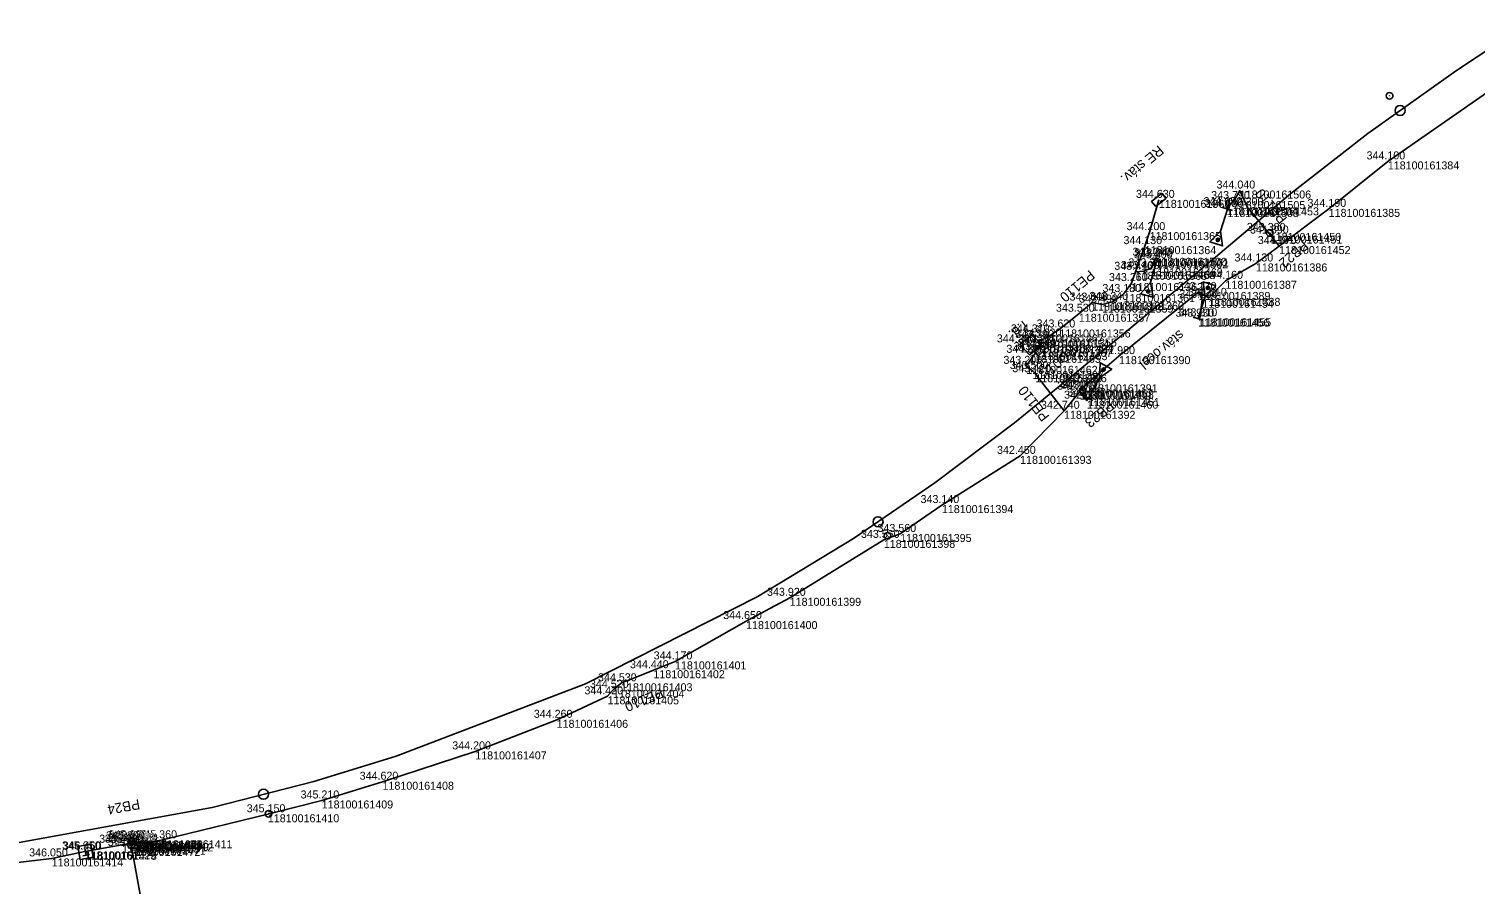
# Model space of a CAD drawing. Extents: x -732194 to -724760, y -944826 to -941477.
# Drawn here: x -726803.1 to -726586.2, y -941994.8 to -941866.5 of the extents above; entities that cross this region are included whole.
import ezdxf

# ---------------------------------------------------------------- set-up
doc = ezdxf.new("R2010")
doc.units = 0
for name, color, linetype in [('Vrstva 1', 7, 'Continuous'), ('Vrstva 25', 7, 'Continuous'), ('Vrstva 26', 7, 'Continuous'), ('Vrstva 28', 7, 'Continuous'), ('Vrstva 31', 7, 'Continuous'), ('Vrstva 33', 7, 'Continuous'), ('Vrstva 35', 7, 'Continuous'), ('Vrstva 36', 7, 'Continuous'), ('Vrstva 4', 7, 'Continuous'), ('Vrstva 6', 7, 'Continuous'), ('Vrstva 60', 7, 'Continuous'), ('Vrstva 61', 7, 'Continuous'), ('Vrstva 7', 7, 'Continuous')]:
    doc.layers.add(name, color=color, linetype=linetype)

msp = doc.modelspace()

# ---------------------------------------------------------------- linework, layer by layer
at = {"layer": 'Vrstva 1'}
msp.add_lwpolyline([(-726579.57, -941866.53), (-726589.02, -941872.75), (-726602.3, -941882.23), (-726613.83, -941891.22), (-726625.12, -941900.77), (-726638.15, -941911.63), (-726655.27, -941925.61), (-726667.22, -941934.63), (-726679.44, -941942.96), (-726693.78, -941951.66), (-726719.62, -941964.76), (-726748.05, -941975.61), (-726760.36, -941979.39), (-726775.65, -941983.31), (-726804.56, -941988.54), (-726832.05, -941990.67), (-726859.67, -941990.82), (-726884.47, -941990.59), (-726908.99, -941990.36), (-726961.75, -941989.93), (-727002.29, -941989.53)], dxfattribs=at)
at = {"layer": 'Vrstva 25'}
for points in [[(-726633.19, -941891.15), (-726632.55, -941891.91), (-726634.09, -941893.19), (-726634.73, -941892.43), (-726633.19, -941891.15)], [(-726650.91, -941913.48), (-726650.25, -941914.23), (-726651.75, -941915.56), (-726652.41, -941914.81), (-726650.91, -941913.48)]]:
    msp.add_lwpolyline(points, dxfattribs=at)
at = {"layer": 'Vrstva 26'}
for points in [[(-726580.39, -941873.25), (-726599.3, -941886.4), (-726608.17, -941893.52), (-726615.6, -941899.1), (-726619.09, -941901.71), (-726623.65, -941904.31), (-726626.12, -941906.87), (-726627.62, -941905.98), (-726639.62, -941915.61), (-726644.54, -941919.84), (-726645.19, -941920.6), (-726645.48, -941920.93), (-726647.86, -941923.81)], [(-726637.12, -941902.96), (-726635.75, -941899.11), (-726635.03, -941897.01), (-726633.64, -941892.17)], [(-726651.33, -941914.52), (-726651.77, -941913.2), (-726650.65, -941912.97), (-726648.58, -941911.61), (-726645.64, -941909.25), (-726643.65, -941907.58), (-726642.16, -941907.88), (-726640.59, -941907.48), (-726638.93, -941906.3), (-726637.72, -941904.65), (-726637.12, -941902.96)], [(-726652.59, -941917.84), (-726653.53, -941917.07), (-726652.06, -941915.01)], [(-726647.86, -941923.81), (-726652.16, -941918.32), (-726652.59, -941917.84)], [(-726647.86, -941923.81), (-726654.45, -941930.57), (-726666.18, -941937.95), (-726672.44, -941942.28), (-726674.89, -941943.17), (-726689.01, -941951.86), (-726695.55, -941955.35), (-726706.21, -941961.4), (-726709.45, -941962.72), (-726714.3, -941964.68), (-726715.51, -941965.66), (-726716.32, -941966.64), (-726723.96, -941970.16), (-726736.17, -941974.9), (-726750.08, -941979.45), (-726759.2, -941982.26), (-726767.28, -941984.33), (-726783.3, -941988.23), (-726786.19, -941988.71), (-726786.85, -941988.6)], [(-726788.31, -941988.87), (-726789.14, -941988.9), (-726794.75, -941989.89)], [(-726786.85, -941988.6), (-726787.32, -941989.21), (-726788.12, -941989.39), (-726788.31, -941988.87)], [(-726794.75, -941989.89), (-726799.69, -941990.95), (-726813.85, -941992.61)]]:
    msp.add_lwpolyline(points, dxfattribs=at)
at = {"layer": 'Vrstva 28'}
for p, q in [((-726617.05, -941897.16), (-726616.97, -941897.1)), ((-726617.01, -941897.13), (-726616.83, -941897.52)), ((-726645.13, -941920.8), (-726645.05, -941920.74)), ((-726787.74, -941988.36), (-726787.64, -941988.34))]:
    msp.add_line(p, q, dxfattribs=at)
for points in [[(-726580.39, -941873.25), (-726599.3, -941886.4), (-726608.17, -941893.52), (-726615.6, -941899.1), (-726619.09, -941901.71), (-726623.65, -941904.31), (-726626.12, -941906.87), (-726627.62, -941905.98), (-726639.62, -941915.61), (-726644.54, -941919.84), (-726645.19, -941920.6), (-726645.48, -941920.93), (-726647.86, -941923.81)], [(-726623.35, -941893.55), (-726623.49, -941893.26), (-726622.39, -941892.35), (-726621.51, -941890.77), (-726620.34, -941893.3)], [(-726616.83, -941897.52), (-726620.34, -941893.3)], [(-726616.83, -941897.52), (-726615.6, -941899.1)], [(-726651.77, -941913.2), (-726650.65, -941912.97), (-726648.58, -941911.61), (-726645.64, -941909.25), (-726643.65, -941907.58), (-726642.16, -941907.88), (-726640.59, -941907.48), (-726638.93, -941906.3), (-726637.72, -941904.65), (-726637.12, -941902.96), (-726635.89, -941902.85), (-726634.77, -941902.44), (-726634.14, -941900.86)], [(-726634.14, -941900.86), (-726633.84, -941900.97), (-726633.96, -941901.24)], [(-726627.62, -941905.98), (-726627.12, -941907.16), (-726627.51, -941909.93), (-726627.76, -941909.99)], [(-726652.59, -941917.84), (-726653.53, -941917.07), (-726652.06, -941915.01)], [(-726647.86, -941923.81), (-726652.16, -941918.32), (-726652.59, -941917.84)], [(-726645.48, -941920.93), (-726644.43, -941922.29), (-726644.21, -941921.9)], [(-726645.19, -941920.6), (-726645.09, -941920.77)], [(-726647.86, -941923.81), (-726654.45, -941930.57), (-726666.18, -941937.95), (-726672.44, -941942.28), (-726674.89, -941943.17), (-726689.01, -941951.86), (-726695.55, -941955.35), (-726706.21, -941961.4), (-726709.45, -941962.72), (-726714.3, -941964.68), (-726715.51, -941965.66), (-726716.32, -941966.64), (-726723.96, -941970.16), (-726736.17, -941974.9), (-726750.08, -941979.45), (-726759.2, -941982.26), (-726767.28, -941984.33), (-726783.3, -941988.23), (-726786.19, -941988.71), (-726786.85, -941988.6)], [(-726788.31, -941988.87), (-726789.14, -941988.9), (-726794.75, -941989.89)], [(-726788.31, -941988.87), (-726788.13, -941988.39), (-726787.81, -941988.23), (-726787.69, -941988.35)], [(-726786.85, -941988.6), (-726787.32, -941989.21), (-726788.12, -941989.39), (-726788.31, -941988.87)], [(-726788.31, -941988.87), (-726787.83, -941988.66)], [(-726794.63, -941989.96), (-726794.75, -941989.89), (-726799.69, -941990.95), (-726813.85, -941992.61)]]:
    msp.add_lwpolyline(points, dxfattribs=at)
for centre in [(-726617.01, -941897.13), (-726645.09, -941920.77), (-726787.69, -941988.35)]:
    msp.add_circle(centre, 0.5, dxfattribs=at)
at = {"layer": 'Vrstva 31'}
for points in [[(-726580.39, -941873.25), (-726599.3, -941886.4), (-726608.17, -941893.52), (-726615.6, -941899.1), (-726619.09, -941901.71), (-726623.65, -941904.31), (-726626.12, -941906.87), (-726627.62, -941905.98), (-726639.62, -941915.61), (-726644.54, -941919.84), (-726645.19, -941920.6), (-726645.48, -941920.93), (-726647.86, -941923.81)], [(-726647.86, -941923.81), (-726654.45, -941930.57), (-726666.18, -941937.95), (-726672.44, -941942.28), (-726674.89, -941943.17), (-726689.01, -941951.86), (-726695.55, -941955.35), (-726706.21, -941961.4), (-726709.45, -941962.72), (-726714.3, -941964.68), (-726715.51, -941965.66), (-726716.32, -941966.64), (-726723.96, -941970.16), (-726736.17, -941974.9), (-726750.08, -941979.45), (-726759.2, -941982.26), (-726767.28, -941984.33), (-726783.3, -941988.23), (-726786.19, -941988.71), (-726786.85, -941988.6)], [(-726788.31, -941988.87), (-726789.14, -941988.9), (-726794.75, -941989.89)], [(-726786.85, -941988.6), (-726787.32, -941989.21), (-726788.12, -941989.39), (-726788.31, -941988.87)], [(-726794.63, -941989.96), (-726794.75, -941989.89), (-726799.69, -941990.95), (-726813.85, -941992.61)]]:
    msp.add_lwpolyline(points, dxfattribs=at)
at = {"layer": 'Vrstva 33'}
for p, q in [((-726794.54, -941990.45), (-726794.72, -941989.47)), ((-726794.05, -941990.36), (-726795.03, -941990.54))]:
    msp.add_line(p, q, dxfattribs=at)
msp.add_lwpolyline([(-726793.47, -941990.77), (-726795.44, -941991.12), (-726795.79, -941989.15), (-726793.82, -941988.8), (-726793.47, -941990.77)], dxfattribs=at)
at = {"layer": 'Vrstva 35'}
for points in [[(-726616.83, -941897.52), (-726620.34, -941893.3)], [(-726651.77, -941913.2), (-726650.65, -941912.97), (-726648.58, -941911.61), (-726645.64, -941909.25), (-726643.65, -941907.58), (-726642.16, -941907.88), (-726640.59, -941907.48), (-726638.93, -941906.3), (-726637.72, -941904.65), (-726637.12, -941902.96), (-726635.89, -941902.85), (-726634.77, -941902.44), (-726634.14, -941900.86)], [(-726623.65, -941904.31), (-726626.12, -941906.87), (-726627.62, -941905.98), (-726639.62, -941915.61)], [(-726647.86, -941923.81), (-726652.16, -941918.32)], [(-726709.45, -941962.72), (-726714.3, -941964.68), (-726715.51, -941965.66)]]:
    msp.add_lwpolyline(points, dxfattribs=at)
at = {"layer": 'Vrstva 36'}
msp.add_lwpolyline([(-726651.19, -941913.97), (-726653.06, -941915.41), (-726654.51, -941913.85), (-726652.63, -941912.35), (-726651.19, -941913.97)], dxfattribs=at)
at = {"layer": 'Vrstva 4'}
for p, q in [((-726622.61, -941893.79), (-726624.09, -941893.31)), ((-726624.58, -941898.06), (-726625.01, -941898.28)), ((-726633.21, -941901.45), (-726634.71, -941901.03)), ((-726626.51, -941905.49), (-726626.07, -941905.27)), ((-726635.02, -941905.79), (-726635.45, -941906.03)), ((-726628.5, -941909.75), (-726627.02, -941910.23)), ((-726642.16, -941917.7), (-726641.69, -941917.56)), ((-726644.89, -941921.53), (-726643.53, -941922.27))]:
    msp.add_line(p, q, dxfattribs=at)
for points in [[(-726623.35, -941893.55), (-726624.41, -941896.86), (-726624.08, -941899.07), (-726625.98, -941898.47), (-726624.41, -941896.86)], [(-726633.96, -941901.24), (-726634.89, -941904.59), (-726634.48, -941906.79), (-726636.41, -941906.26), (-726634.89, -941904.59)], [(-726627.76, -941909.99), (-726626.68, -941906.68), (-726627, -941904.47), (-726625.1, -941905.08), (-726626.68, -941906.68)], [(-726644.21, -941921.9), (-726642.55, -941918.85), (-726642.46, -941916.61), (-726640.7, -941917.56), (-726642.55, -941918.85)]]:
    msp.add_lwpolyline(points, dxfattribs=at)
for centre in [(-726624.79, -941898.17), (-726626.29, -941905.38), (-726635.23, -941905.91), (-726641.92, -941917.63)]:
    msp.add_circle(centre, 0.248, dxfattribs=at)
at = {"layer": 'Vrstva 6'}
for p, q in [((-726787.92, -941988.17), (-726787.74, -941989.15)), ((-726785.88, -941988.31), (-726787.83, -941988.66)), ((-726778.93, -942037.86), (-726787.83, -941988.66))]:
    msp.add_line(p, q, dxfattribs=at)
at = {"layer": 'Vrstva 60'}
for p, q in [((-726599.3, -941886.4), (-726599.3, -941886.4)), ((-726633.64, -941892.17), (-726633.64, -941892.17)), ((-726621.51, -941890.77), (-726621.51, -941890.77)), ((-726623.49, -941893.26), (-726623.49, -941893.26)), ((-726623.35, -941893.55), (-726623.35, -941893.55)), ((-726622.39, -941892.35), (-726622.39, -941892.35)), ((-726620.34, -941893.3), (-726620.34, -941893.3)), ((-726608.17, -941893.52), (-726608.17, -941893.52)), ((-726635.03, -941897.01), (-726635.03, -941897.01)), ((-726617.01, -941897.13), (-726617.01, -941897.13)), ((-726616.83, -941897.52), (-726616.83, -941897.52)), ((-726635.75, -941899.11), (-726635.75, -941899.11)), ((-726634.14, -941900.86), (-726634.14, -941900.86)), ((-726615.6, -941899.1), (-726615.6, -941899.1)), ((-726637.12, -941902.96), (-726637.12, -941902.96)), ((-726635.89, -941902.85), (-726635.89, -941902.85)), ((-726634.77, -941902.44), (-726634.77, -941902.44)), ((-726633.96, -941901.24), (-726633.96, -941901.24)), ((-726633.84, -941900.97), (-726633.84, -941900.97)), ((-726619.09, -941901.71), (-726619.09, -941901.71)), ((-726637.72, -941904.65), (-726637.72, -941904.65)), ((-726623.65, -941904.31), (-726623.65, -941904.31)), ((-726638.93, -941906.3), (-726638.93, -941906.3)), ((-726627.62, -941905.98), (-726627.62, -941905.98)), ((-726627.12, -941907.16), (-726627.12, -941907.16)), ((-726626.12, -941906.87), (-726626.12, -941906.87)), ((-726645.64, -941909.25), (-726645.64, -941909.25)), ((-726643.65, -941907.58), (-726643.65, -941907.58)), ((-726642.16, -941907.88), (-726642.16, -941907.88)), ((-726640.59, -941907.48), (-726640.59, -941907.48)), ((-726648.58, -941911.61), (-726648.58, -941911.61)), ((-726627.76, -941909.99), (-726627.76, -941909.99)), ((-726627.51, -941909.93), (-726627.51, -941909.93)), ((-726654.51, -941913.85), (-726654.51, -941913.85)), ((-726652.63, -941912.35), (-726652.63, -941912.35)), ((-726651.77, -941913.2), (-726651.77, -941913.2)), ((-726650.65, -941912.97), (-726650.65, -941912.97)), ((-726653.06, -941915.41), (-726653.06, -941915.41)), ((-726652.06, -941915.01), (-726652.06, -941915.01)), ((-726651.33, -941914.52), (-726651.33, -941914.52)), ((-726651.19, -941913.97), (-726651.19, -941913.97)), ((-726639.62, -941915.61), (-726639.62, -941915.61)), ((-726653.53, -941917.07), (-726653.53, -941917.07)), ((-726652.59, -941917.84), (-726652.59, -941917.84)), ((-726652.16, -941918.32), (-726652.16, -941918.32)), ((-726644.54, -941919.84), (-726644.54, -941919.84)), ((-726645.48, -941920.93), (-726645.48, -941920.93)), ((-726645.19, -941920.6), (-726645.19, -941920.6)), ((-726645.09, -941920.77), (-726645.09, -941920.77)), ((-726644.43, -941922.29), (-726644.43, -941922.29)), ((-726644.21, -941921.9), (-726644.21, -941921.9)), ((-726647.86, -941923.81), (-726647.86, -941923.81)), ((-726654.45, -941930.57), (-726654.45, -941930.57)), ((-726666.18, -941937.95), (-726666.18, -941937.95)), ((-726674.89, -941943.17), (-726674.89, -941943.17)), ((-726672.44, -941942.28), (-726672.44, -941942.28)), ((-726689.01, -941951.86), (-726689.01, -941951.86)), ((-726695.55, -941955.35), (-726695.55, -941955.35)), ((-726706.21, -941961.4), (-726706.21, -941961.4)), ((-726709.45, -941962.72), (-726709.45, -941962.72)), ((-726715.51, -941965.66), (-726715.51, -941965.66)), ((-726714.3, -941964.68), (-726714.3, -941964.68)), ((-726716.32, -941966.64), (-726716.32, -941966.64)), ((-726723.96, -941970.16), (-726723.96, -941970.16)), ((-726736.17, -941974.9), (-726736.17, -941974.9)), ((-726750.08, -941979.45), (-726750.08, -941979.45)), ((-726759.2, -941982.26), (-726759.2, -941982.26)), ((-726767.28, -941984.33), (-726767.28, -941984.33)), ((-726789.14, -941988.9), (-726789.14, -941988.9)), ((-726788.31, -941988.87), (-726788.31, -941988.87)), ((-726788.13, -941988.39), (-726788.13, -941988.39)), ((-726788.12, -941989.39), (-726788.12, -941989.39)), ((-726787.83, -941988.66), (-726787.83, -941988.66)), ((-726787.81, -941988.23), (-726787.81, -941988.23)), ((-726787.69, -941988.35), (-726787.69, -941988.35)), ((-726787.32, -941989.21), (-726787.32, -941989.21)), ((-726786.85, -941988.6), (-726786.85, -941988.6)), ((-726786.19, -941988.71), (-726786.19, -941988.71)), ((-726783.3, -941988.23), (-726783.3, -941988.23)), ((-726799.69, -941990.95), (-726799.69, -941990.95)), ((-726794.75, -941989.89), (-726794.75, -941989.89)), ((-726794.63, -941989.96), (-726794.63, -941989.96))]:
    msp.add_line(p, q, dxfattribs=at)
at = {"layer": 'Vrstva 7'}
for p, q in [((-726599.07, -941876.6), (-726598.99, -941876.54)), ((-726674.37, -941942.59), (-726674.28, -941942.53)), ((-726767.23, -941984.28), (-726767.13, -941984.25))]:
    msp.add_line(p, q, dxfattribs=at)
for centre, radius in [((-726599.03, -941876.57), 0.5), ((-726597.46, -941878.77), 0.75), ((-726675.76, -941940.45), 0.75), ((-726674.32, -941942.56), 0.5), ((-726767.93, -941981.33), 0.75), ((-726767.18, -941984.26), 0.5)]:
    msp.add_circle(centre, radius, dxfattribs=at)

# ---------------------------------------------------------------- texts
at = {"layer": 'Vrstva 25'}
for s, rotation, p in [('RE stáv.', 219.8056, (-726633.7, -941883.9)), ('RO01', 221.6335, (-726646.73, -941913.76))]:
    msp.add_text(s, height=1.5, rotation=rotation, dxfattribs=at).set_placement(p)
at = {"layer": 'Vrstva 28'}
for s, rotation, p in [('PB22', 220.2486, (-726612.02, -941898.18)), ('PB23', 219.2246, (-726641.1, -941922.2)), ('PB24', 190.2527, (-726786.62, -941982.06))]:
    msp.add_text(s, height=1.5, rotation=rotation, dxfattribs=at).set_placement(p)
at = {"layer": 'Vrstva 36'}
for s, rotation, p in [('PE110', 129.7521, (-726614.31, -941894.97)), ('PE110', 220.0032, (-726644.04, -941902.62)), ('r.d.', 217.5982, (-726654.04, -941910.21)), ('stáv.ocel', 218.747, (-726630.55, -941911.59)), ('PE110', 128.0695, (-726649.96, -941924.65)), ('PE110', 202.0048, (-726708.33, -941965.35))]:
    msp.add_text(s, height=1.5, rotation=rotation, dxfattribs=at).set_placement(p)
at = {"layer": 'Vrstva 6'}
msp.add_text('  A A A A ', height=1, rotation=10.2527, dxfattribs=at).set_placement((-726787.65, -941989.64))
at = {"layer": 'Vrstva 60'}
for s, p in [('118100161384', (-726599.3, -941887.6)), ('118100161366', (-726633.64, -941893.37)), ('118100161506', (-726621.51, -941891.97)), ('118100161504', (-726623.49, -941894.46)), ('118100161503', (-726623.35, -941894.75)), ('118100161505', (-726622.39, -941893.55)), ('118100161453', (-726620.34, -941894.5)), ('118100161385', (-726608.17, -941894.72)), ('118100161365', (-726635.03, -941898.21)), ('118100161450', (-726617.01, -941898.33)), ('118100161451', (-726616.83, -941898.72)), ('118100161364', (-726635.75, -941900.31)), ('118100161500', (-726634.14, -941902.06)), ('118100161501', (-726633.84, -941902.17)), ('118100161452', (-726615.6, -941900.3)), ('118100161363', (-726637.12, -941904.16)), ('118100161468', (-726635.89, -941904.05)), ('118100161469', (-726634.77, -941903.64)), ('118100161502', (-726633.96, -941902.44)), ('118100161386', (-726619.09, -941902.91)), ('118100161362', (-726637.72, -941905.85)), ('118100161387', (-726623.65, -941905.51)), ('118100161360', (-726640.59, -941908.68)), ('118100161361', (-726638.93, -941907.5)), ('118100161389', (-726627.62, -941907.18)), ('118100161454', (-726627.12, -941908.36)), ('118100161388', (-726626.12, -941908.07)), ('118100161357', (-726645.64, -941910.45)), ('118100161358', (-726643.65, -941908.78)), ('118100161359', (-726642.16, -941909.08)), ('118100161356', (-726648.58, -941912.81)), ('118100161456', (-726627.76, -941911.19)), ('118100161455', (-726627.51, -941911.13)), ('118100161466', (-726654.51, -941915.05)), ('118100161467', (-726652.63, -941913.55)), ('118100161354', (-726651.77, -941914.4)), ('118100161464', (-726651.19, -941915.17)), ('118100161355', (-726650.65, -941914.17)), ('118100161465', (-726653.06, -941916.61)), ('118100161463', (-726652.06, -941916.21)), ('118100161367', (-726651.33, -941915.72)), ('118100161390', (-726639.62, -941916.81)), ('118100161462', (-726653.53, -941918.27)), ('118100161397', (-726652.59, -941919.04)), ('118100161396', (-726652.16, -941919.52)), ('118100161391', (-726644.54, -941921.04)), ('118100161459', (-726645.48, -941922.13)), ('118100161457', (-726645.19, -941921.8)), ('118100161458', (-726645.09, -941921.97)), ('118100161460', (-726644.43, -941923.49)), ('118100161461', (-726644.21, -941923.1)), ('118100161392', (-726647.86, -941925.01)), ('118100161393', (-726654.45, -941931.77)), ('118100161394', (-726666.18, -941939.15)), ('118100161398', (-726674.89, -941944.37)), ('118100161395', (-726672.44, -941943.48)), ('118100161399', (-726689.01, -941953.06)), ('118100161400', (-726695.55, -941956.55)), ('118100161401', (-726706.21, -941962.6)), ('118100161402', (-726709.45, -941963.92)), ('118100161404', (-726715.51, -941966.86)), ('118100161403', (-726714.3, -941965.88)), ('118100161405', (-726716.32, -941967.84)), ('118100161406', (-726723.96, -941971.36)), ('118100161407', (-726736.17, -941976.1)), ('118100161408', (-726750.08, -941980.65)), ('118100161409', (-726759.2, -941983.46)), ('118100161410', (-726767.28, -941985.53)), ('118100161529', (-726794.75, -941991.09)), ('118100161413', (-726789.14, -941990.1)), ('118100161473', (-726788.31, -941990.07)), ('118100161474', (-726788.13, -941989.59)), ('118100161472', (-726788.12, -941990.59)), ('118100161477', (-726787.83, -941989.86)), ('118100161475', (-726787.81, -941989.43)), ('118100161476', (-726787.69, -941989.55)), ('118100161471', (-726787.32, -941990.41)), ('118100161470', (-726786.85, -941989.8)), ('118100161412', (-726786.19, -941989.91)), ('118100161411', (-726783.3, -941989.43)), ('118100161414', (-726799.69, -941992.15)), ('118100161478', (-726794.63, -941991.16))]:
    msp.add_text(s, height=1.2, dxfattribs=at).set_placement(p)
at = {"layer": 'Vrstva 61'}
for s, p in [('344.100', (-726602.49, -941886.1)), ('344.040', (-726624.99, -941890.47)), ('344.630', (-726637.07, -941891.87)), ('344.050', (-726626.94, -941892.96)), ('344.630', (-726626.78, -941893.25)), ('343.790', (-726625.79, -941892.05)), ('342.200', (-726623.76, -941893)), ('344.190', (-726611.34, -941893.22)), ('344.200', (-726638.48, -941896.71)), ('343.380', (-726620.44, -941896.83)), ('341.890', (-726619.97, -941897.22)), ('344.130', (-726638.95, -941898.81)), ('344.170', (-726618.8, -941898.8)), ('343.330', (-726638.2, -941902.14)), ('343.240', (-726637.6, -941900.56)), ('343.800', (-726637.38, -941900.94)), ('343.240', (-726637.3, -941900.67)), ('344.130', (-726622.29, -941901.41)), ('343.410', (-726640.32, -941902.66)), ('343.400', (-726639.34, -941902.55)), ('344.160', (-726626.82, -941904.01)), ('343.180', (-726642.1, -941906)), ('343.260', (-726641.12, -941904.35)), ('343.170', (-726630.79, -941905.68)), ('343.600', (-726647.04, -941907.28)), ('343.490', (-726645.59, -941907.58)), ('343.340', (-726644.05, -941907.18)), ('343.240', (-726630.58, -941906.86)), ('343.610', (-726629.26, -941906.57)), ('343.530', (-726649.07, -941908.95)), ('343.930', (-726631.16, -941909.69)), ('343.310', (-726630.68, -941909.63)), ('344.310', (-726655.83, -941912.05)), ('343.390', (-726655.17, -941912.9)), ('343.620', (-726654.05, -941912.67)), ('343.620', (-726651.98, -941911.31)), ('344.260', (-726657.94, -941913.55)), ('344.300', (-726656.51, -941915.11)), ('343.690', (-726655.43, -941914.71)), ('344.340', (-726654.81, -941914.22)), ('344.280', (-726654.65, -941913.67)), ('343.200', (-726656.95, -941916.77)), ('342.980', (-726643.02, -941915.31)), ('343.500', (-726656.01, -941917.54)), ('343.420', (-726655.62, -941918.02)), ('342.970', (-726648.88, -941920.63)), ('343.080', (-726648.61, -941920.3)), ('343.710', (-726648.26, -941920.47)), ('342.790', (-726647.94, -941919.54)), ('343.180', (-726647.38, -941921.6)), ('342.740', (-726651.32, -941923.51)), ('342.530', (-726647.86, -941921.99)), ('342.450', (-726657.91, -941930.27)), ('343.140', (-726669.38, -941937.65)), ('343.550', (-726678.32, -941942.87)), ('343.560', (-726675.84, -941941.98)), ('343.920', (-726692.41, -941951.56)), ('344.650', (-726698.98, -941955.05)), ('344.440', (-726712.96, -941962.42)), ('344.170', (-726709.41, -941961.1)), ('344.530', (-726717.76, -941964.38)), ('344.420', (-726719.8, -941966.34)), ('344.520', (-726718.97, -941965.36)), ('344.260', (-726727.39, -941969.86)), ('344.200', (-726739.62, -941974.6)), ('344.620', (-726753.51, -941979.15)), ('345.210', (-726762.37, -941981.96)), ('345.150', (-726770.45, -941984.03)), ('345.490', (-726792.57, -941988.6)), ('345.080', (-726791.73, -941988.57)), ('345.200', (-726791.55, -941988.09)), ('346.430', (-726791.26, -941988.36)), ('345.660', (-726791.18, -941987.93)), ('346.500', (-726791.08, -941988.05)), ('345.210', (-726790.49, -941988.91)), ('345.190', (-726789.99, -941988.3)), ('345.350', (-726789.62, -941988.41)), ('345.360', (-726786.7, -941987.93)), ('346.050', (-726803.08, -941990.65)), ('345.950', (-726798.15, -941989.59)), ('346.460', (-726798.03, -941989.66)), ('345.310', (-726791.29, -941989.09))]:
    msp.add_text(s, height=1.2, dxfattribs=at).set_placement(p)

doc.saveas('drawing.dxf')
